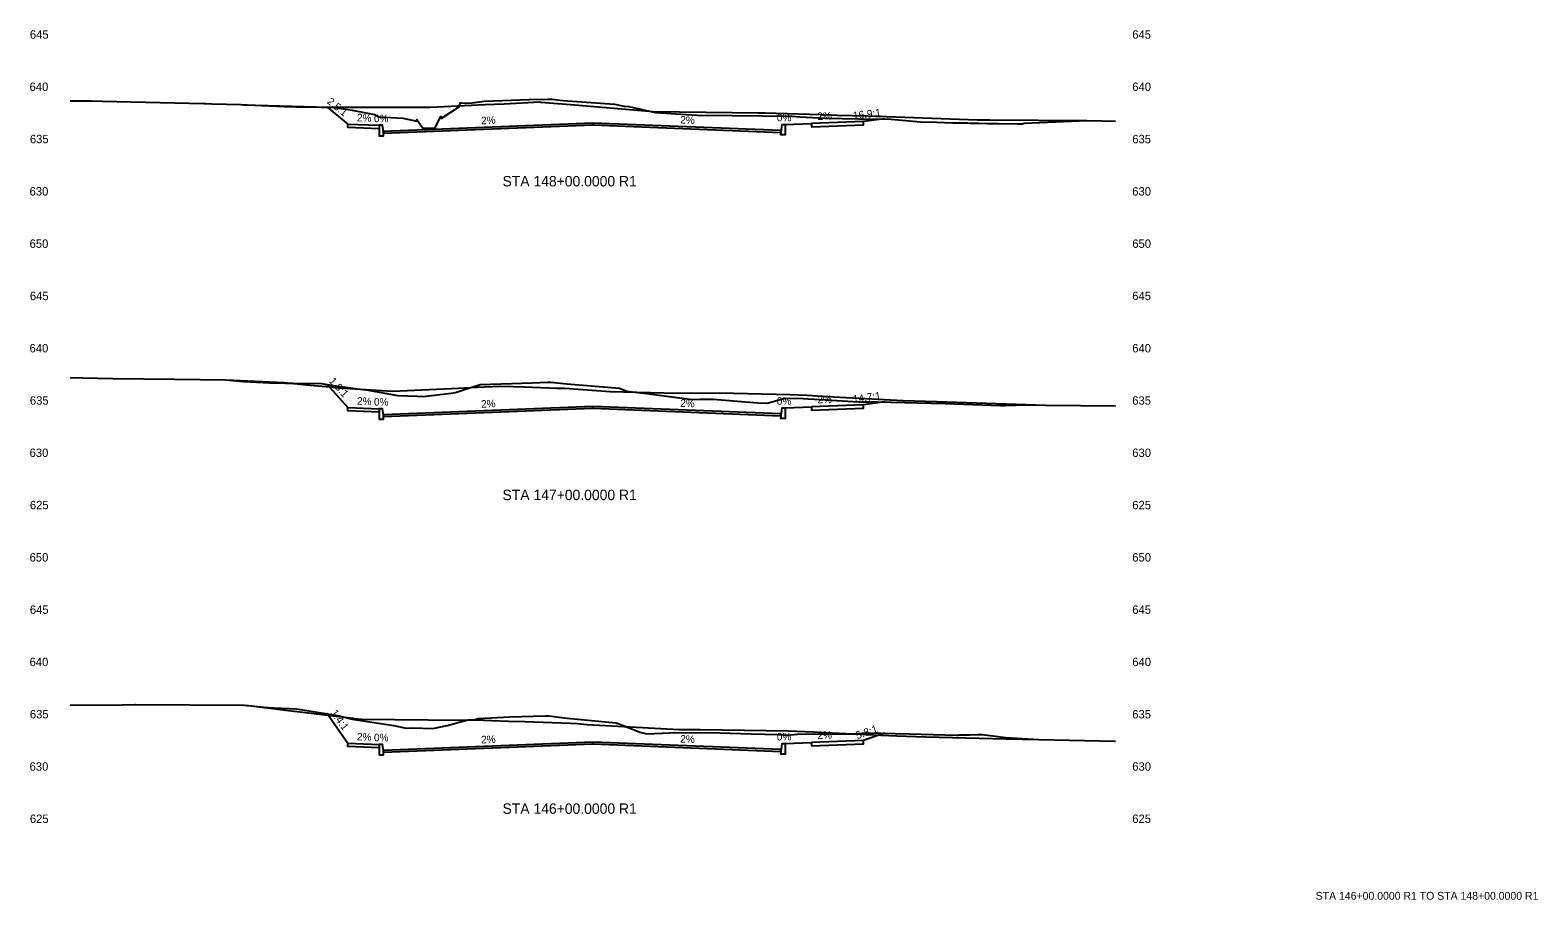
# Model space of a CAD drawing. Extents: x 12 to 301, y 16 to 1707.
# Drawn here: x 12.4 to 300.8, y 1140.9 to 1307.2 of the extents above; entities that cross this region are included whole.
import ezdxf

# ---------------------------------------------------------------- set-up
doc = ezdxf.new("R2010")
doc.units = 0
for name, color, linetype in [('BORD_text_large_2', 7, 'Continuous'), ('Default', 7, 'Continuous'), ('Draft_XS_Point_Label_Indicator', 7, 'Continuous'), ('Draft_XS_Text', 7, 'Continuous'), ('Grade_Veg_Grass', 7, 'Continuous'), ('P_XS_Sections', 7, 'Continuous'), ('Road_Curb', 7, 'Continuous'), ('Road_Pave_Asphalt', 7, 'Continuous'), ('Road_Sidewalk', 7, 'Continuous'), ('Terrain_Exterior', 7, 'Continuous')]:
    doc.layers.add(name, color=color, linetype=linetype)

msp = doc.modelspace()

# ---------------------------------------------------------------- linework, layer by layer
at = {"layer": 'Default'}
for points in [[(20, 1293.74), (24.13, 1293.71), (26.17, 1293.68), (45.61, 1293.2), (45.99, 1293.19), (47.1, 1293.17), (52.66, 1293), (53.2, 1292.98), (53.87, 1292.93), (60.96, 1292.62), (63.23, 1292.58), (69.21, 1292.49), (69.91, 1292.48), (70.62, 1292.47), (70.69, 1292.47), (74.01, 1291.93), (78.27, 1291.1), (79, 1290.65), (83.65, 1290.43), (86.33, 1289.81), (86.37, 1290.12), (87.48, 1288.49), (89.77, 1288.48), (90.93, 1290.75), (90.98, 1290.33), (94.53, 1292.61), (94.65, 1293.3), (94.66, 1293.32), (94.81, 1293.32), (95.51, 1293.29), (95.56, 1293.29), (95.68, 1293.3), (96.86, 1293.36), (99.29, 1293.65), (107.87, 1293.95), (111.41, 1294.05), (112.18, 1294.04), (112.19, 1294.03), (112.21, 1294.03), (112.21, 1294.03), (113.21, 1293.89), (114.26, 1293.77), (120.62, 1293.36), (124.15, 1293.11), (124.47, 1293.04), (125.96, 1292.7), (126.08, 1292.7), (126.91, 1292.66), (132.04, 1291.48), (139.95, 1290.97), (146.65, 1290.92), (158.13, 1290.76), (159.65, 1290.68), (164.52, 1290.42), (174.03, 1290.23), (176.42, 1290.28), (182.73, 1289.72), (185.78, 1289.64), (188.85, 1289.53), (188.88, 1289.53), (189.04, 1289.53), (189.2, 1289.52), (189.3, 1289.52), (189.46, 1289.52), (189.54, 1289.52), (189.94, 1289.51), (190.18, 1289.51), (190.44, 1289.5), (191.02, 1289.49), (191.75, 1289.48), (192.17, 1289.47), (192.21, 1289.47), (192.64, 1289.46), (193.64, 1289.44), (193.84, 1289.44), (195.5, 1289.41), (196.48, 1289.39), (197.63, 1289.37), (201.3, 1289.3), (202.18, 1289.29), (202.56, 1289.42), (214.52, 1289.94), (217.47, 1289.88), (220, 1289.84)], [(20, 1240.81), (22.47, 1240.75), (28.19, 1240.6), (40.07, 1240.46), (49.79, 1240.36), (53.2, 1240.03), (58.16, 1239.8), (58.91, 1239.79), (59.64, 1239.77), (59.85, 1239.77), (60.04, 1239.77), (60.18, 1239.76), (60.39, 1239.76), (60.55, 1239.76), (60.64, 1239.75), (60.74, 1239.75), (60.79, 1239.75), (60.83, 1239.75), (60.98, 1239.75), (61.04, 1239.75), (61.1, 1239.75), (61.16, 1239.74), (61.18, 1239.74), (61.22, 1239.74), (61.3, 1239.74), (61.37, 1239.74), (61.4, 1239.74), (62.67, 1239.7), (68.13, 1239.64), (70.41, 1239.26), (74.55, 1238.72), (77.01, 1238.35), (82.71, 1237.33), (86.39, 1237.21), (87.58, 1237.18), (92.89, 1237.8), (93.73, 1237.96), (94.87, 1238.29), (94.92, 1238.29), (98.49, 1239.44), (108.39, 1239.81), (111.33, 1239.9), (111.41, 1239.89), (111.49, 1239.9), (111.96, 1239.89), (115.06, 1239.6), (125.14, 1238.79), (126.55, 1238.21), (130.31, 1237.77), (139.01, 1236.58), (140.52, 1236.66), (143.02, 1236.67), (151.6, 1235.98), (153.4, 1235.92), (156.79, 1236.83), (157.37, 1236.79), (159.19, 1236.83), (170.9, 1236.15), (174.55, 1236.17), (184.76, 1235.9), (187.46, 1235.82), (197.92, 1235.45), (198.32, 1235.46), (198.82, 1235.47), (199.19, 1235.48), (199.47, 1235.49), (200.98, 1235.53), (202.62, 1235.58), (206.64, 1235.53), (220, 1235.37)], [(20, 1178.16), (29.99, 1178.22), (32.47, 1178.24), (32.56, 1178.24), (53.29, 1178.12), (53.88, 1178.1), (54.16, 1178.07), (57.67, 1177.7), (57.94, 1177.68), (58.38, 1177.65), (58.75, 1177.62), (58.97, 1177.61), (59.04, 1177.61), (63.34, 1177.46), (71.22, 1176.17), (73.98, 1175.45), (81.92, 1174.24), (84.29, 1173.76), (85.51, 1173.82), (89.4, 1173.7), (92.18, 1174.23), (96.12, 1175.31), (97.24, 1175.33), (98.06, 1175.61), (98.18, 1175.61), (104.05, 1175.88), (110.91, 1176.1), (111.28, 1176.1), (111.43, 1176.1), (111.52, 1176.09), (111.58, 1176.1), (115.14, 1175.67), (124.4, 1174.77), (124.48, 1174.67), (124.77, 1174.7), (128.99, 1172.96), (130.33, 1172.63), (134.76, 1172.86), (142.27, 1172.89), (150.3, 1172.68), (155.48, 1172.51), (157.2, 1172.39), (159.18, 1172.58), (169.73, 1172.64), (172.43, 1172.87), (180.61, 1172.64), (189.6, 1172.41), (189.89, 1172.42), (189.94, 1172.42), (189.96, 1172.42), (190.05, 1172.43), (190.14, 1172.43), (190.73, 1172.44), (191.5, 1172.46), (191.79, 1172.47), (191.84, 1172.47), (191.92, 1172.48), (192.15, 1172.48), (193.69, 1172.52), (194.53, 1172.55), (199.04, 1171.96), (205.35, 1171.55), (219.86, 1171.26), (220, 1171.26)]]:
    msp.add_lwpolyline(points, dxfattribs=at)
at = {"layer": 'Grade_Veg_Grass'}
for points in [[(69.17, 1292.49), (69.17, 1292.49), (73.17, 1289.27)], [(156.83, 1289.19), (161.83, 1289.39)], [(175.83, 1290.27), (175.83, 1290.27), (171.83, 1289.79)], [(69.17, 1239.46), (69.17, 1239.46), (73.17, 1235.07)], [(156.83, 1234.99), (161.83, 1235.19)], [(175.83, 1236.14), (175.83, 1236.14), (171.83, 1235.59)], [(69.17, 1176.51), (69.17, 1176.51), (73.17, 1170.87)], [(175.83, 1172.77), (175.83, 1172.77), (171.83, 1171.39)], [(156.83, 1170.79), (161.83, 1170.99)]]:
    msp.add_lwpolyline(points, dxfattribs=at)
at = {"layer": 'Road_Curb'}
for points in [[(79.17, 1289.03), (79.17, 1287.03), (80, 1287.03), (80, 1287.87), (79.77, 1289.03), (79.17, 1289.03)], [(156.83, 1289.19), (156.83, 1287.19), (156, 1287.19), (156.23, 1289.19), (156.83, 1289.19)], [(79.17, 1234.83), (79.17, 1232.83), (80, 1232.83), (80, 1233.67), (79.77, 1234.83), (79.17, 1234.83)], [(156.83, 1234.99), (156.83, 1232.99), (156, 1232.99), (156.23, 1234.99), (156.83, 1234.99)], [(79.17, 1170.63), (79.17, 1168.63), (80, 1168.63), (80, 1169.47), (79.77, 1170.63), (79.17, 1170.63)], [(156.83, 1170.79), (156.83, 1168.79), (156, 1168.79), (156.23, 1170.79), (156.83, 1170.79)]]:
    msp.add_lwpolyline(points, dxfattribs=at)
at = {"layer": 'Road_Pave_Asphalt'}
for points in [[(120, 1289.47), (80, 1287.87), (80, 1287.87), (80, 1287.53), (120, 1289.13), (120, 1289.13), (120, 1289.47), (120, 1289.47), (120, 1289.47)], [(120, 1289.47), (120, 1289.47), (120, 1289.47), (120, 1289.13), (120, 1289.13), (156, 1287.69), (156, 1288.03), (156, 1288.03), (120, 1289.47)], [(120, 1235.27), (80, 1233.67), (80, 1233.67), (80, 1233.33), (120, 1234.93), (120, 1234.93), (120, 1235.27), (120, 1235.27), (120, 1235.27)], [(120, 1235.27), (120, 1235.27), (120, 1235.27), (120, 1234.93), (120, 1234.93), (156, 1233.49), (156, 1233.83), (156, 1233.83), (120, 1235.27)], [(120, 1171.07), (80, 1169.47), (80, 1169.47), (80, 1169.13), (120, 1170.73), (120, 1170.73), (120, 1171.07), (120, 1171.07), (120, 1171.07)], [(120, 1171.07), (120, 1171.07), (120, 1171.07), (120, 1170.73), (120, 1170.73), (156, 1169.29), (156, 1169.63), (156, 1169.63), (120, 1171.07)]]:
    msp.add_lwpolyline(points, dxfattribs=at)
at = {"layer": 'Road_Sidewalk'}
for points in [[(161.83, 1289.39), (161.83, 1288.73), (171.83, 1289.13), (171.83, 1289.79), (161.83, 1289.39)], [(79.17, 1289.03), (79.17, 1288.37), (73.17, 1288.61), (73.17, 1289.27), (79.17, 1289.03)], [(79.17, 1234.83), (79.17, 1234.17), (73.17, 1234.41), (73.17, 1235.07), (79.17, 1234.83)], [(161.83, 1235.19), (161.83, 1234.53), (171.83, 1234.93), (171.83, 1235.59), (161.83, 1235.19)], [(161.83, 1170.99), (161.83, 1170.33), (171.83, 1170.73), (171.83, 1171.39), (161.83, 1170.99)], [(79.17, 1170.63), (79.17, 1169.97), (73.17, 1170.21), (73.17, 1170.87), (79.17, 1170.63)]]:
    msp.add_lwpolyline(points, dxfattribs=at)
at = {"layer": 'Terrain_Exterior'}
for points in [[(20, 1293.74), (24.13, 1293.71), (26.17, 1293.68), (45.61, 1293.2), (45.99, 1293.19), (47.1, 1293.17), (52.66, 1293), (53.2, 1292.98), (67.09, 1292.55), (68.02, 1292.48), (88.58, 1292.48), (88.95, 1292.51), (99.42, 1293), (99.44, 1293), (103.09, 1293.17), (109.88, 1293.5), (110.06, 1293.49), (115.78, 1293), (115.81, 1293), (130.81, 1291.72), (130.88, 1291.71), (131.54, 1291.67), (151.73, 1291.41), (153.02, 1291.39), (165.67, 1291.03), (166.74, 1291), (172.66, 1290.83), (174.01, 1290.8), (174.51, 1290.78), (193.59, 1290.07), (195.99, 1290.05), (214.52, 1289.94), (217.47, 1289.88), (220, 1289.84)], [(20, 1240.81), (22.47, 1240.75), (28.19, 1240.6), (40.07, 1240.46), (49.79, 1240.36), (60.89, 1239.82), (65.93, 1239.36), (69.79, 1239), (71.38, 1238.85), (73.52, 1238.72), (81.71, 1238.21), (88.7, 1238.51), (92.98, 1238.7), (99.25, 1239), (102.53, 1239.16), (106.98, 1239), (113.16, 1238.78), (114.58, 1238.73), (123.35, 1238.1), (136.18, 1237.81), (144.18, 1237.85), (157.78, 1237.58), (161, 1237.41), (165, 1237.19), (168.46, 1237), (172.19, 1236.79), (179.38, 1236.39), (185.82, 1236.2), (200.98, 1235.7), (206.64, 1235.53), (220, 1235.37)], [(20, 1178.16), (29.99, 1178.22), (32.47, 1178.24), (32.56, 1178.24), (53.29, 1178.12), (54.16, 1178.08), (62.83, 1177.01), (62.94, 1177), (74.11, 1175.63), (74.29, 1175.61), (75.76, 1175.47), (94.93, 1175.24), (97.36, 1175.32), (103.91, 1175.1), (107.03, 1175), (115.75, 1174.71), (117.04, 1174.6), (118.96, 1174.42), (136.57, 1173.45), (140.55, 1173.45), (157.39, 1173.25), (162.15, 1173.05), (163.16, 1173), (175.15, 1172.39), (178.21, 1172.24), (183.75, 1172.06), (199.04, 1171.68), (205.35, 1171.55), (219.86, 1171.26), (220, 1171.26)]]:
    msp.add_lwpolyline(points, dxfattribs=at)

# ---------------------------------------------------------------- texts
at = {"layer": 'BORD_text_large_2'}
msp.add_text('STA 146+00.0000 R1 TO STA 148+00.0000 R1', height=1.5, dxfattribs=at).set_placement((258.32, 1140.92))
at = {"layer": 'Draft_XS_Point_Label_Indicator'}
for p in [(69.16, 1292.48), (119.99, 1289.46), (119.99, 1289.46), (161.82, 1289.38), (171.82, 1289.78), (175.82, 1290.26), (73.16, 1289.26), (79.16, 1289.02), (79.76, 1289.02), (79.99, 1287.86), (155.99, 1288.02), (156.22, 1289.18), (156.82, 1289.18), (69.16, 1239.45), (73.16, 1235.06), (79.16, 1234.82), (79.76, 1234.82), (119.99, 1235.26), (119.99, 1235.26), (156.22, 1234.98), (156.82, 1234.98), (161.82, 1235.18), (171.82, 1235.58), (175.82, 1236.13), (79.99, 1233.66), (155.99, 1233.82), (69.16, 1176.49), (119.99, 1171.06), (119.99, 1171.06), (171.82, 1171.38), (175.82, 1172.76), (73.16, 1170.86), (79.16, 1170.62), (79.76, 1170.62), (79.99, 1169.46), (155.99, 1169.62), (156.22, 1170.78), (156.82, 1170.78), (161.82, 1170.98)]:
    msp.add_text('X', height=0.024, dxfattribs=at).set_placement(p)
at = {"layer": 'Draft_XS_Text'}
for s, height, p in [('645', 1.608, (12.32, 1305.6)), ('645', 1.608, (223.22, 1305.6)), ('640', 1.608, (12.26, 1295.6)), ('640', 1.608, (223.22, 1295.6)), ('635', 1.608, (12.32, 1285.6)), ('635', 1.608, (223.22, 1285.6)), ('STA 148+00.0000 R1', 1.992, (102.74, 1277.35)), ('630', 1.608, (12.26, 1275.6)), ('630', 1.608, (223.22, 1275.6)), ('650', 1.608, (12.26, 1265.6)), ('650', 1.608, (223.22, 1265.6)), ('645', 1.608, (12.32, 1255.6)), ('645', 1.608, (223.22, 1255.6)), ('640', 1.608, (12.26, 1245.6)), ('640', 1.608, (223.22, 1245.6)), ('635', 1.608, (12.32, 1235.6)), ('0%', 1.44, (155.22, 1235.59)), ('0%', 1.44, (155.22, 1235.59)), ('0%', 1.44, (155.22, 1235.59)), ('635', 1.608, (223.22, 1235.6)), ('630', 1.608, (12.26, 1225.6)), ('630', 1.608, (223.22, 1225.6)), ('625', 1.608, (12.32, 1215.6)), ('STA 147+00.0000 R1', 1.992, (102.74, 1217.35)), ('625', 1.608, (223.22, 1215.6)), ('650', 1.608, (12.26, 1205.6)), ('650', 1.608, (223.22, 1205.6)), ('645', 1.608, (12.32, 1195.6)), ('645', 1.608, (223.22, 1195.6)), ('640', 1.608, (12.26, 1185.6)), ('640', 1.608, (223.22, 1185.6)), ('635', 1.608, (12.32, 1175.6)), ('635', 1.608, (223.22, 1175.6)), ('630', 1.608, (12.26, 1165.6)), ('630', 1.608, (223.22, 1165.6)), ('625', 1.608, (12.32, 1155.6)), ('STA 146+00.0000 R1', 1.992, (102.74, 1157.35)), ('625', 1.608, (223.22, 1155.6))]:
    msp.add_text(s, height=height, dxfattribs=at).set_placement(p)
for s, rotation, p in [('2.5:1', 321.1754, (69.05, 1293.36)), ('2.5:1', 321.1754, (69.05, 1293.36)), ('2.5:1', 321.1754, (69.05, 1293.36)), ('2%', 357.7094, (74.88, 1289.81)), ('2%', 357.7094, (74.88, 1289.81)), ('2%', 357.7094, (74.88, 1289.81)), ('0%', 0, (78.15, 1289.63)), ('0%', 0, (78.15, 1289.63)), ('0%', 0, (78.15, 1289.63)), ('2%', 2.2906, (98.66, 1289.21)), ('2%', 2.2906, (98.66, 1289.21)), ('2%', 2.2906, (98.66, 1289.21)), ('2%', 357.7094, (136.71, 1289.4)), ('2%', 357.7094, (136.71, 1289.4)), ('2%', 357.7094, (136.71, 1289.4)), ('0%', 0, (155.22, 1289.79)), ('0%', 0, (155.22, 1289.79)), ('0%', 0, (155.22, 1289.79)), ('2%', 2.2906, (163, 1290.04)), ('2%', 2.2906, (163, 1290.04)), ('2%', 2.2906, (163, 1290.04)), ('16.9:1', 6.7657, (169.88, 1290.17)), ('16.9:1', 6.7657, (169.88, 1290.17)), ('16.9:1', 6.7657, (169.88, 1290.17)), ('1.8:1', 312.3412, (69.46, 1240.04)), ('1.8:1', 312.3412, (69.46, 1240.04)), ('1.8:1', 312.3412, (69.46, 1240.04)), ('14.7:1', 7.7356, (169.88, 1235.93)), ('14.7:1', 7.7356, (169.88, 1235.93)), ('14.7:1', 7.7356, (169.88, 1235.93)), ('2%', 357.7094, (74.88, 1235.61)), ('2%', 357.7094, (74.88, 1235.61)), ('2%', 357.7094, (74.88, 1235.61)), ('0%', 0, (78.15, 1235.43)), ('0%', 0, (78.15, 1235.43)), ('0%', 0, (78.15, 1235.43)), ('2%', 2.2906, (98.66, 1235.01)), ('2%', 2.2906, (98.66, 1235.01)), ('2%', 2.2906, (98.66, 1235.01)), ('2%', 357.7094, (136.71, 1235.2)), ('2%', 357.7094, (136.71, 1235.2)), ('2%', 357.7094, (136.71, 1235.2)), ('2%', 2.2906, (163, 1235.84)), ('2%', 2.2906, (163, 1235.84)), ('2%', 2.2906, (163, 1235.84)), ('1.4:1', 305.3883, (69.8, 1176.65)), ('1.4:1', 305.3883, (69.8, 1176.65)), ('1.4:1', 305.3883, (69.8, 1176.65)), ('5.8:1', 19.0355, (170.61, 1171.61)), ('5.8:1', 19.0355, (170.61, 1171.61)), ('5.8:1', 19.0355, (170.61, 1171.61)), ('2%', 357.7094, (74.88, 1171.41)), ('2%', 357.7094, (74.88, 1171.41)), ('2%', 357.7094, (74.88, 1171.41)), ('0%', 0, (78.15, 1171.23)), ('0%', 0, (78.15, 1171.23)), ('0%', 0, (78.15, 1171.23)), ('2%', 2.2906, (98.66, 1170.81)), ('2%', 2.2906, (98.66, 1170.81)), ('2%', 2.2906, (98.66, 1170.81)), ('2%', 357.7094, (136.71, 1171)), ('2%', 357.7094, (136.71, 1171)), ('2%', 357.7094, (136.71, 1171)), ('0%', 0, (155.22, 1171.39)), ('0%', 0, (155.22, 1171.39)), ('0%', 0, (155.22, 1171.39)), ('2%', 2.2906, (163, 1171.64)), ('2%', 2.2906, (163, 1171.64)), ('2%', 2.2906, (163, 1171.64))]:
    msp.add_text(s, height=1.44, rotation=rotation, dxfattribs=at).set_placement(p)
at = {"layer": 'P_XS_Sections'}
for p in [(20, 1275), (20, 1215), (20, 1155)]:
    msp.add_text('-', height=0.0001, dxfattribs=at).set_placement(p)

doc.saveas('drawing.dxf')
